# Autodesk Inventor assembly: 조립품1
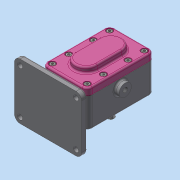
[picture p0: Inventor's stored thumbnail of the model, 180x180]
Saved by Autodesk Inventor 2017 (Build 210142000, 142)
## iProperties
Part Number: 조립품1
Material: 일반
Document SubType Name: Assembly
Designer: MRC
Author: MRC
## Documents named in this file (11)
- C:\Users\MRC\Desktop\700407V1045\조립품1.iam
- C:\Users\MRC\Desktop\700407V1045\Ű 6 x 6 x 18.ipt
- C:\Users\MRC\Desktop\700407V1045\개스킷.ipt
- C:\Users\MRC\Desktop\700407V1045\메인축.ipt
- C:\Users\MRC\Desktop\700407V1045\베어링부시.ipt
- C:\Users\MRC\Desktop\700407V1045\본체.ipt
- C:\Users\MRC\Desktop\700407V1045\볼트 M5.ipt
- C:\Users\MRC\Desktop\700407V1045\서브축.ipt
- C:\Users\MRC\Desktop\700407V1045\스퍼기어.ipt
- C:\Users\MRC\Desktop\700407V1045\오일 실 16 28 7.ipt
- C:\Users\MRC\Desktop\700407V1045\커버.ipt
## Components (3 placed, 2 different names)
1. Ű 6 x 6 x 18:1
2. 개스킷:1
3. Ű 6 x 6 x 18:2
